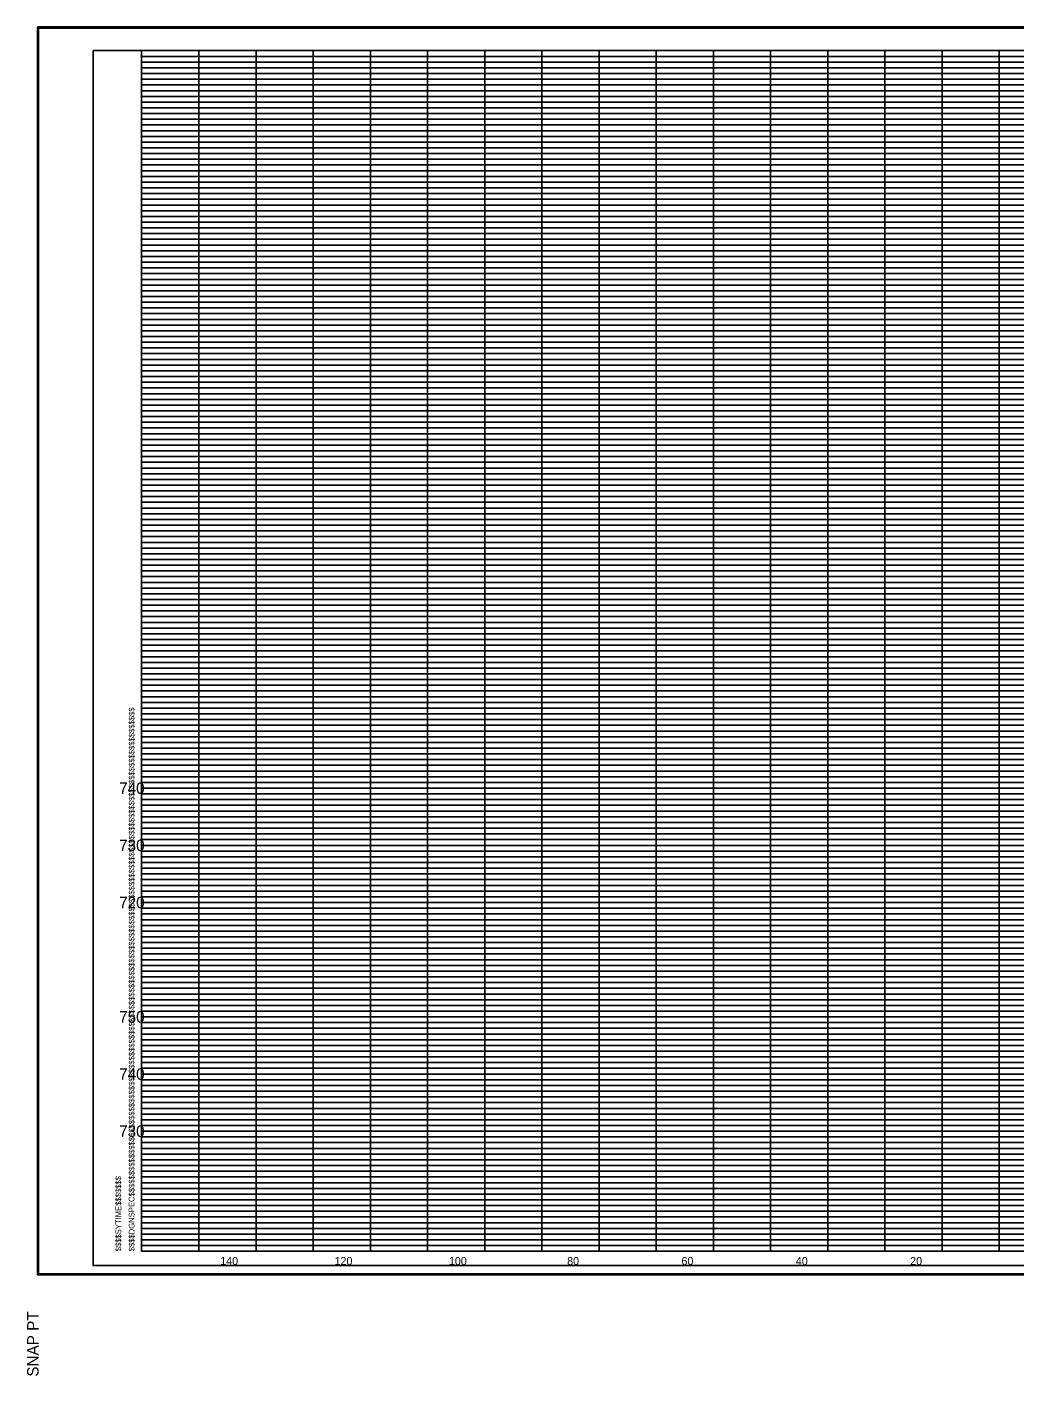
# Model space of a CAD drawing. Extents: x -200 to 1704, y -325 to 2307.
# Drawn here: x 1359.9 to 1532.6, y 1248.2 to 1484.1 of the extents above; entities that cross this region are included whole.
import ezdxf

# ---------------------------------------------------------------- set-up
doc = ezdxf.new("R2010")
doc.units = 0
for name, color, linetype in [('DESIGN - SHEET - Corner Text', 7, 'Continuous'), ('DESIGN - SHEET - Light Grid', 7, 'Continuous'), ('DESIGN - SHEET - Linework', 7, 'Continuous'), ('DESIGN - SHEET - Plot Shape', 7, 'Continuous'), ('DESIGN - TYPICAL - Text', 7, 'Continuous')]:
    doc.layers.add(name, color=color, linetype=linetype)

msp = doc.modelspace()

# ---------------------------------------------------------------- linework, layer by layer
at = {"layer": 'DESIGN - SHEET - Light Grid'}
for p, q in [((1380, 1479), (1460, 1479)), ((1380, 1478), (1460, 1478)), ((1460, 1479), (1540, 1479)), ((1460, 1478), (1540, 1478)), ((1380, 1477), (1460, 1477)), ((1380, 1476), (1460, 1476)), ((1380, 1475), (1460, 1475)), ((1460, 1477), (1540, 1477)), ((1460, 1476), (1540, 1476)), ((1460, 1475), (1540, 1475)), ((1380, 1474), (1460, 1474)), ((1380, 1473), (1460, 1473)), ((1460, 1474), (1540, 1474)), ((1460, 1473), (1540, 1473)), ((1380, 1472), (1460, 1472)), ((1380, 1471), (1460, 1471)), ((1460, 1472), (1540, 1472)), ((1460, 1471), (1540, 1471)), ((1380, 1469), (1460, 1469)), ((1380, 1468), (1460, 1468)), ((1460, 1469), (1540, 1469)), ((1460, 1468), (1540, 1468)), ((1380, 1467), (1460, 1467)), ((1380, 1466), (1460, 1466)), ((1460, 1467), (1540, 1467)), ((1460, 1466), (1540, 1466)), ((1380, 1465), (1460, 1465)), ((1380, 1464), (1460, 1464)), ((1380, 1463), (1460, 1463)), ((1460, 1465), (1540, 1465)), ((1460, 1464), (1540, 1464)), ((1460, 1463), (1540, 1463)), ((1380, 1462), (1460, 1462)), ((1380, 1461), (1460, 1461)), ((1460, 1462), (1540, 1462)), ((1460, 1461), (1540, 1461)), ((1380, 1459), (1460, 1459)), ((1460, 1459), (1540, 1459)), ((1380, 1458), (1460, 1458)), ((1380, 1457), (1460, 1457)), ((1380, 1456), (1460, 1456)), ((1460, 1458), (1540, 1458)), ((1460, 1457), (1540, 1457)), ((1460, 1456), (1540, 1456)), ((1380, 1455), (1460, 1455)), ((1380, 1454), (1460, 1454)), ((1460, 1455), (1540, 1455)), ((1460, 1454), (1540, 1454)), ((1380, 1453), (1460, 1453)), ((1380, 1452), (1460, 1452)), ((1460, 1453), (1540, 1453)), ((1460, 1452), (1540, 1452)), ((1380, 1451), (1460, 1451)), ((1380, 1449), (1460, 1449)), ((1460, 1451), (1540, 1451)), ((1460, 1449), (1540, 1449)), ((1380, 1448), (1460, 1448)), ((1380, 1447), (1460, 1447)), ((1460, 1448), (1540, 1448)), ((1460, 1447), (1540, 1447)), ((1380, 1446), (1460, 1446)), ((1380, 1445), (1460, 1445)), ((1460, 1446), (1540, 1446)), ((1460, 1445), (1540, 1445)), ((1380, 1444), (1460, 1444)), ((1380, 1443), (1460, 1443)), ((1380, 1442), (1460, 1442)), ((1460, 1444), (1540, 1444)), ((1460, 1443), (1540, 1443)), ((1460, 1442), (1540, 1442)), ((1380, 1441), (1460, 1441)), ((1460, 1441), (1540, 1441)), ((1380, 1439), (1460, 1439)), ((1380, 1438), (1460, 1438)), ((1380, 1437), (1460, 1437)), ((1460, 1439), (1540, 1439)), ((1460, 1438), (1540, 1438)), ((1460, 1437), (1540, 1437)), ((1380, 1436), (1460, 1436)), ((1380, 1435), (1460, 1435)), ((1460, 1436), (1540, 1436)), ((1460, 1435), (1540, 1435)), ((1380, 1434), (1460, 1434)), ((1380, 1433), (1460, 1433)), ((1460, 1434), (1540, 1434)), ((1460, 1433), (1540, 1433)), ((1380, 1432), (1460, 1432)), ((1380, 1431), (1460, 1431)), ((1460, 1432), (1540, 1432)), ((1460, 1431), (1540, 1431)), ((1380, 1429), (1460, 1429)), ((1380, 1428), (1460, 1428)), ((1460, 1429), (1540, 1429)), ((1460, 1428), (1540, 1428)), ((1380, 1427), (1460, 1427)), ((1380, 1426), (1460, 1426)), ((1460, 1427), (1540, 1427)), ((1460, 1426), (1540, 1426)), ((1380, 1425), (1460, 1425)), ((1380, 1424), (1460, 1424)), ((1380, 1423), (1460, 1423)), ((1460, 1425), (1540, 1425)), ((1460, 1424), (1540, 1424)), ((1460, 1423), (1540, 1423)), ((1380, 1422), (1460, 1422)), ((1380, 1421), (1460, 1421)), ((1460, 1422), (1540, 1422)), ((1460, 1421), (1540, 1421)), ((1380, 1419), (1460, 1419)), ((1460, 1419), (1540, 1419)), ((1380, 1418), (1460, 1418)), ((1380, 1417), (1460, 1417)), ((1380, 1416), (1460, 1416)), ((1460, 1418), (1540, 1418)), ((1460, 1417), (1540, 1417)), ((1460, 1416), (1540, 1416)), ((1380, 1415), (1460, 1415)), ((1380, 1414), (1460, 1414)), ((1460, 1415), (1540, 1415)), ((1460, 1414), (1540, 1414)), ((1380, 1413), (1460, 1413)), ((1380, 1412), (1460, 1412)), ((1460, 1413), (1540, 1413)), ((1460, 1412), (1540, 1412)), ((1380, 1411), (1460, 1411)), ((1380, 1409), (1460, 1409)), ((1460, 1411), (1540, 1411)), ((1460, 1409), (1540, 1409)), ((1380, 1408), (1460, 1408)), ((1380, 1407), (1460, 1407)), ((1460, 1408), (1540, 1408)), ((1460, 1407), (1540, 1407)), ((1380, 1406), (1460, 1406)), ((1380, 1405), (1460, 1405)), ((1380, 1404), (1460, 1404)), ((1460, 1406), (1540, 1406)), ((1460, 1405), (1540, 1405)), ((1460, 1404), (1540, 1404)), ((1380, 1403), (1460, 1403)), ((1380, 1402), (1460, 1402)), ((1460, 1403), (1540, 1403)), ((1460, 1402), (1540, 1402)), ((1380, 1401), (1460, 1401)), ((1460, 1401), (1540, 1401)), ((1380, 1399), (1460, 1399)), ((1380, 1398), (1460, 1398)), ((1380, 1397), (1460, 1397)), ((1460, 1399), (1540, 1399)), ((1460, 1398), (1540, 1398)), ((1460, 1397), (1540, 1397)), ((1380, 1396), (1460, 1396)), ((1380, 1395), (1460, 1395)), ((1460, 1396), (1540, 1396)), ((1460, 1395), (1540, 1395)), ((1380, 1394), (1460, 1394)), ((1380, 1393), (1460, 1393)), ((1460, 1394), (1540, 1394)), ((1460, 1393), (1540, 1393)), ((1380, 1392), (1460, 1392)), ((1380, 1391), (1460, 1391)), ((1460, 1392), (1540, 1392)), ((1460, 1391), (1540, 1391)), ((1380, 1389), (1460, 1389)), ((1380, 1388), (1460, 1388)), ((1460, 1389), (1540, 1389)), ((1460, 1388), (1540, 1388)), ((1380, 1387), (1460, 1387)), ((1380, 1386), (1460, 1386)), ((1460, 1387), (1540, 1387)), ((1460, 1386), (1540, 1386)), ((1380, 1385), (1460, 1385)), ((1380, 1384), (1460, 1384)), ((1380, 1383), (1460, 1383)), ((1460, 1385), (1540, 1385)), ((1460, 1384), (1540, 1384)), ((1460, 1383), (1540, 1383)), ((1380, 1382), (1460, 1382)), ((1380, 1381), (1460, 1381)), ((1460, 1382), (1540, 1382)), ((1460, 1381), (1540, 1381)), ((1380, 1379), (1460, 1379)), ((1380, 1378), (1460, 1378)), ((1460, 1379), (1540, 1379)), ((1460, 1378), (1540, 1378)), ((1380, 1377), (1460, 1377)), ((1380, 1376), (1460, 1376)), ((1460, 1377), (1540, 1377)), ((1460, 1376), (1540, 1376)), ((1380, 1375), (1460, 1375)), ((1380, 1374), (1460, 1374)), ((1460, 1375), (1540, 1375)), ((1460, 1374), (1540, 1374)), ((1380, 1373), (1460, 1373)), ((1380, 1372), (1460, 1372)), ((1380, 1371), (1460, 1371)), ((1460, 1373), (1540, 1373)), ((1460, 1372), (1540, 1372)), ((1460, 1371), (1540, 1371)), ((1380, 1369), (1460, 1369)), ((1460, 1369), (1540, 1369)), ((1380, 1368), (1460, 1368)), ((1380, 1367), (1460, 1367)), ((1460, 1368), (1540, 1368)), ((1460, 1367), (1540, 1367)), ((1380, 1366), (1460, 1366)), ((1380, 1365), (1460, 1365)), ((1380, 1364), (1460, 1364)), ((1460, 1366), (1540, 1366)), ((1460, 1365), (1540, 1365)), ((1460, 1364), (1540, 1364)), ((1380, 1363), (1460, 1363)), ((1380, 1362), (1460, 1362)), ((1460, 1363), (1540, 1363)), ((1460, 1362), (1540, 1362)), ((1380, 1361), (1460, 1361)), ((1460, 1361), (1540, 1361)), ((1380, 1359), (1460, 1359)), ((1380, 1358), (1460, 1358)), ((1380, 1357), (1460, 1357)), ((1460, 1359), (1540, 1359)), ((1460, 1358), (1540, 1358)), ((1460, 1357), (1540, 1357)), ((1380, 1356), (1460, 1356)), ((1380, 1355), (1460, 1355)), ((1460, 1356), (1540, 1356)), ((1460, 1355), (1540, 1355)), ((1380, 1354), (1460, 1354)), ((1380, 1353), (1460, 1353)), ((1460, 1354), (1540, 1354)), ((1460, 1353), (1540, 1353)), ((1380, 1352), (1460, 1352)), ((1380, 1351), (1460, 1351)), ((1460, 1352), (1540, 1352)), ((1460, 1351), (1540, 1351)), ((1380, 1349), (1460, 1349)), ((1380, 1348), (1460, 1348)), ((1460, 1349), (1540, 1349)), ((1460, 1348), (1540, 1348)), ((1380, 1347), (1460, 1347)), ((1380, 1346), (1460, 1346)), ((1380, 1345), (1460, 1345)), ((1460, 1347), (1540, 1347)), ((1460, 1346), (1540, 1346)), ((1460, 1345), (1540, 1345)), ((1380, 1344), (1460, 1344)), ((1380, 1343), (1460, 1343)), ((1460, 1344), (1540, 1344)), ((1460, 1343), (1540, 1343)), ((1380, 1342), (1460, 1342)), ((1380, 1341), (1460, 1341)), ((1460, 1342), (1540, 1342)), ((1460, 1341), (1540, 1341)), ((1380, 1339), (1460, 1339)), ((1380, 1338), (1460, 1338)), ((1460, 1339), (1540, 1339)), ((1460, 1338), (1540, 1338)), ((1380, 1337), (1460, 1337)), ((1380, 1336), (1460, 1336)), ((1460, 1337), (1540, 1337)), ((1460, 1336), (1540, 1336)), ((1380, 1335), (1460, 1335)), ((1380, 1334), (1460, 1334)), ((1460, 1335), (1540, 1335)), ((1460, 1334), (1540, 1334)), ((1380, 1333), (1460, 1333)), ((1380, 1332), (1460, 1332)), ((1380, 1331), (1460, 1331)), ((1460, 1333), (1540, 1333)), ((1460, 1332), (1540, 1332)), ((1460, 1331), (1540, 1331)), ((1380, 1329), (1460, 1329)), ((1460, 1329), (1540, 1329)), ((1380, 1328), (1460, 1328)), ((1380, 1327), (1460, 1327)), ((1460, 1328), (1540, 1328)), ((1460, 1327), (1540, 1327)), ((1380, 1326), (1460, 1326)), ((1380, 1325), (1460, 1325)), ((1380, 1324), (1460, 1324)), ((1460, 1326), (1540, 1326)), ((1460, 1325), (1540, 1325)), ((1460, 1324), (1540, 1324)), ((1380, 1323), (1460, 1323)), ((1380, 1322), (1460, 1322)), ((1460, 1323), (1540, 1323)), ((1460, 1322), (1540, 1322)), ((1380, 1321), (1460, 1321)), ((1460, 1321), (1540, 1321)), ((1380, 1319), (1460, 1319)), ((1380, 1318), (1460, 1318)), ((1380, 1317), (1460, 1317)), ((1460, 1319), (1540, 1319)), ((1460, 1318), (1540, 1318)), ((1460, 1317), (1540, 1317)), ((1380, 1316), (1460, 1316)), ((1380, 1315), (1460, 1315)), ((1460, 1316), (1540, 1316)), ((1460, 1315), (1540, 1315)), ((1380, 1314), (1460, 1314)), ((1380, 1313), (1460, 1313)), ((1380, 1312), (1460, 1312)), ((1460, 1314), (1540, 1314)), ((1460, 1313), (1540, 1313)), ((1460, 1312), (1540, 1312)), ((1380, 1311), (1460, 1311)), ((1460, 1311), (1540, 1311)), ((1380, 1309), (1460, 1309)), ((1380, 1308), (1460, 1308)), ((1460, 1309), (1540, 1309)), ((1460, 1308), (1540, 1308)), ((1380, 1307), (1460, 1307)), ((1380, 1306), (1460, 1306)), ((1380, 1305), (1460, 1305)), ((1460, 1307), (1540, 1307)), ((1460, 1306), (1540, 1306)), ((1460, 1305), (1540, 1305)), ((1380, 1304), (1460, 1304)), ((1380, 1303), (1460, 1303)), ((1460, 1304), (1540, 1304)), ((1460, 1303), (1540, 1303)), ((1380, 1302), (1460, 1302)), ((1380, 1301), (1460, 1301)), ((1460, 1302), (1540, 1302)), ((1460, 1301), (1540, 1301)), ((1380, 1299), (1460, 1299)), ((1380, 1298), (1460, 1298)), ((1460, 1299), (1540, 1299)), ((1460, 1298), (1540, 1298)), ((1380, 1297), (1460, 1297)), ((1380, 1296), (1460, 1296)), ((1460, 1297), (1540, 1297)), ((1460, 1296), (1540, 1296)), ((1380, 1295), (1460, 1295)), ((1380, 1294), (1460, 1294)), ((1460, 1295), (1540, 1295)), ((1460, 1294), (1540, 1294)), ((1380, 1293), (1460, 1293)), ((1380, 1292), (1460, 1292)), ((1380, 1291), (1460, 1291)), ((1460, 1293), (1540, 1293)), ((1460, 1292), (1540, 1292)), ((1460, 1291), (1540, 1291)), ((1380, 1289), (1460, 1289)), ((1460, 1289), (1540, 1289)), ((1380, 1288), (1460, 1288)), ((1380, 1287), (1460, 1287)), ((1380, 1286), (1460, 1286)), ((1460, 1288), (1540, 1288)), ((1460, 1287), (1540, 1287)), ((1460, 1286), (1540, 1286)), ((1380, 1285), (1460, 1285)), ((1380, 1284), (1460, 1284)), ((1460, 1285), (1540, 1285)), ((1460, 1284), (1540, 1284)), ((1380, 1283), (1460, 1283)), ((1380, 1282), (1460, 1282)), ((1460, 1283), (1540, 1283)), ((1460, 1282), (1540, 1282)), ((1380, 1281), (1460, 1281)), ((1380, 1279), (1460, 1279)), ((1460, 1281), (1540, 1281)), ((1460, 1279), (1540, 1279)), ((1380, 1278), (1460, 1278)), ((1380, 1277), (1460, 1277)), ((1460, 1278), (1540, 1278)), ((1460, 1277), (1540, 1277)), ((1380, 1276), (1460, 1276)), ((1380, 1275), (1460, 1275)), ((1460, 1276), (1540, 1276)), ((1460, 1275), (1540, 1275)), ((1380, 1274), (1460, 1274)), ((1380, 1273), (1460, 1273)), ((1380, 1272), (1460, 1272)), ((1460, 1274), (1540, 1274)), ((1460, 1273), (1540, 1273)), ((1460, 1272), (1540, 1272)), ((1380, 1271), (1460, 1271)), ((1460, 1271), (1540, 1271))]:
    msp.add_line(p, q, dxfattribs=at)
at = {"layer": 'DESIGN - SHEET - Linework'}
for p, q in [((1361.77, 1265.86), (1361.77, 1484.14)), ((1361.77, 1484.14), (1702.17, 1484.14)), ((1390, 1270), (1390, 1480)), ((1400, 1270), (1400, 1480)), ((1410, 1270), (1410, 1480)), ((1420, 1270), (1420, 1480)), ((1430, 1270), (1430, 1480)), ((1440, 1270), (1440, 1480)), ((1450, 1270), (1450, 1480)), ((1460, 1270), (1460, 1480)), ((1470, 1270), (1470, 1480)), ((1480, 1270), (1480, 1480)), ((1490, 1270), (1490, 1480)), ((1500, 1270), (1500, 1480)), ((1510, 1270), (1510, 1480)), ((1520, 1270), (1520, 1480)), ((1530, 1270), (1530, 1480)), ((1380, 1470), (1660, 1470)), ((1380, 1460), (1700, 1460)), ((1380, 1450), (1700, 1450)), ((1380, 1440), (1700, 1440)), ((1380, 1430), (1700, 1430)), ((1380, 1420), (1700, 1420)), ((1380, 1410), (1700, 1410)), ((1380, 1400), (1700, 1400)), ((1380, 1390), (1700, 1390)), ((1380, 1380), (1700, 1380)), ((1380, 1370), (1700, 1370)), ((1380, 1360), (1700, 1360)), ((1380, 1350), (1700, 1350)), ((1380, 1340), (1700, 1340)), ((1380, 1330), (1700, 1330)), ((1380, 1320), (1700, 1320)), ((1380, 1310), (1700, 1310)), ((1380, 1300), (1700, 1300)), ((1380, 1290), (1700, 1290)), ((1380, 1280), (1700, 1280)), ((1361.77, 1265.86), (1702.17, 1265.86))]:
    msp.add_line(p, q, dxfattribs=at)
msp.add_lwpolyline([(1380, 1480), (1380, 1270), (1700, 1270), (1700, 1480), (1380, 1480)], dxfattribs=at)
at = {"layer": 'DESIGN - SHEET - Plot Shape'}
for points in [[(1361.97, 1483.94), (1701.97, 1483.94), (1701.97, 1266.06), (1361.97, 1266.06)], [(1371.5, 1480), (1700, 1480), (1700, 1267.5), (1371.5, 1267.5)]]:
    msp.add_lwpolyline(points, close=True, dxfattribs=at)

# ---------------------------------------------------------------- texts
at = {"layer": 'DESIGN - SHEET - Corner Text'}
for s, height, p in [('$$$$DGNSPEC$$$$$$$$$$$$$$$$$$$$$$$$$$$$$$$$$$$$$$$$$$$$$$$$$$$$$$$$$$$$$$$$$$$$$$$$$$$$$$$$$$$$$$$$$$$$$$$$$$$$$$$$$$$$$$$$$$$', 1.00002, (1378.74, 1270)), ('$$$$SYTIME$$$$$$$', 1, (1376.42, 1270)), ('SNAP PT  ', 2, (1361.97, 1248.06))]:
    msp.add_text(s, height=height, rotation=90, dxfattribs=at).set_placement(p)
at = {"layer": 'DESIGN - TYPICAL - Text'}
for s, height, p in [('     740     ', 2, (1372.34, 1350)), ('     730     ', 2, (1372.34, 1340)), ('     720     ', 2, (1372.34, 1330)), ('     750     ', 2, (1372.34, 1310)), ('     740     ', 2, (1372.34, 1300)), ('     730     ', 2, (1372.34, 1290)), ('     140     ', 1.4, (1391.14, 1267.6)), ('     120     ', 1.4, (1411.14, 1267.6)), ('     100     ', 1.4, (1431.14, 1267.6)), ('     80     ', 1.4, (1451.82, 1267.6)), ('     60     ', 1.4, (1471.82, 1267.6)), ('     40     ', 1.4, (1491.82, 1267.6)), ('     20     ', 1.4, (1511.82, 1267.6))]:
    msp.add_text(s, height=height, dxfattribs=at).set_placement(p)

doc.saveas('drawing.dxf')
